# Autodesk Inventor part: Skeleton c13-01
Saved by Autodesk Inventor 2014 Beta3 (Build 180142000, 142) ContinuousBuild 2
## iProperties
Created: 2011-01
Part Number: Skeleton c13-01
Material: Generic
Document SubType Name: Modeling
Designer: Thom Tremblay
Density: 1 g/cm^3
Appearance: Generic
_SkeletonDoc: Frame Skeleton File
_Version: 15.0.0
Author: Thom Tremblay
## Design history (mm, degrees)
sketch "Reference Skeleton"
  geometry: L1 through (75, 55) direction (1, 0); L2 through (15, 160) direction (1, -0); L3 through (15, 190) direction (1, 0); L4 through (75, 295) direction (1, 0); 33 other entities
  constraints: 20 horizontal
